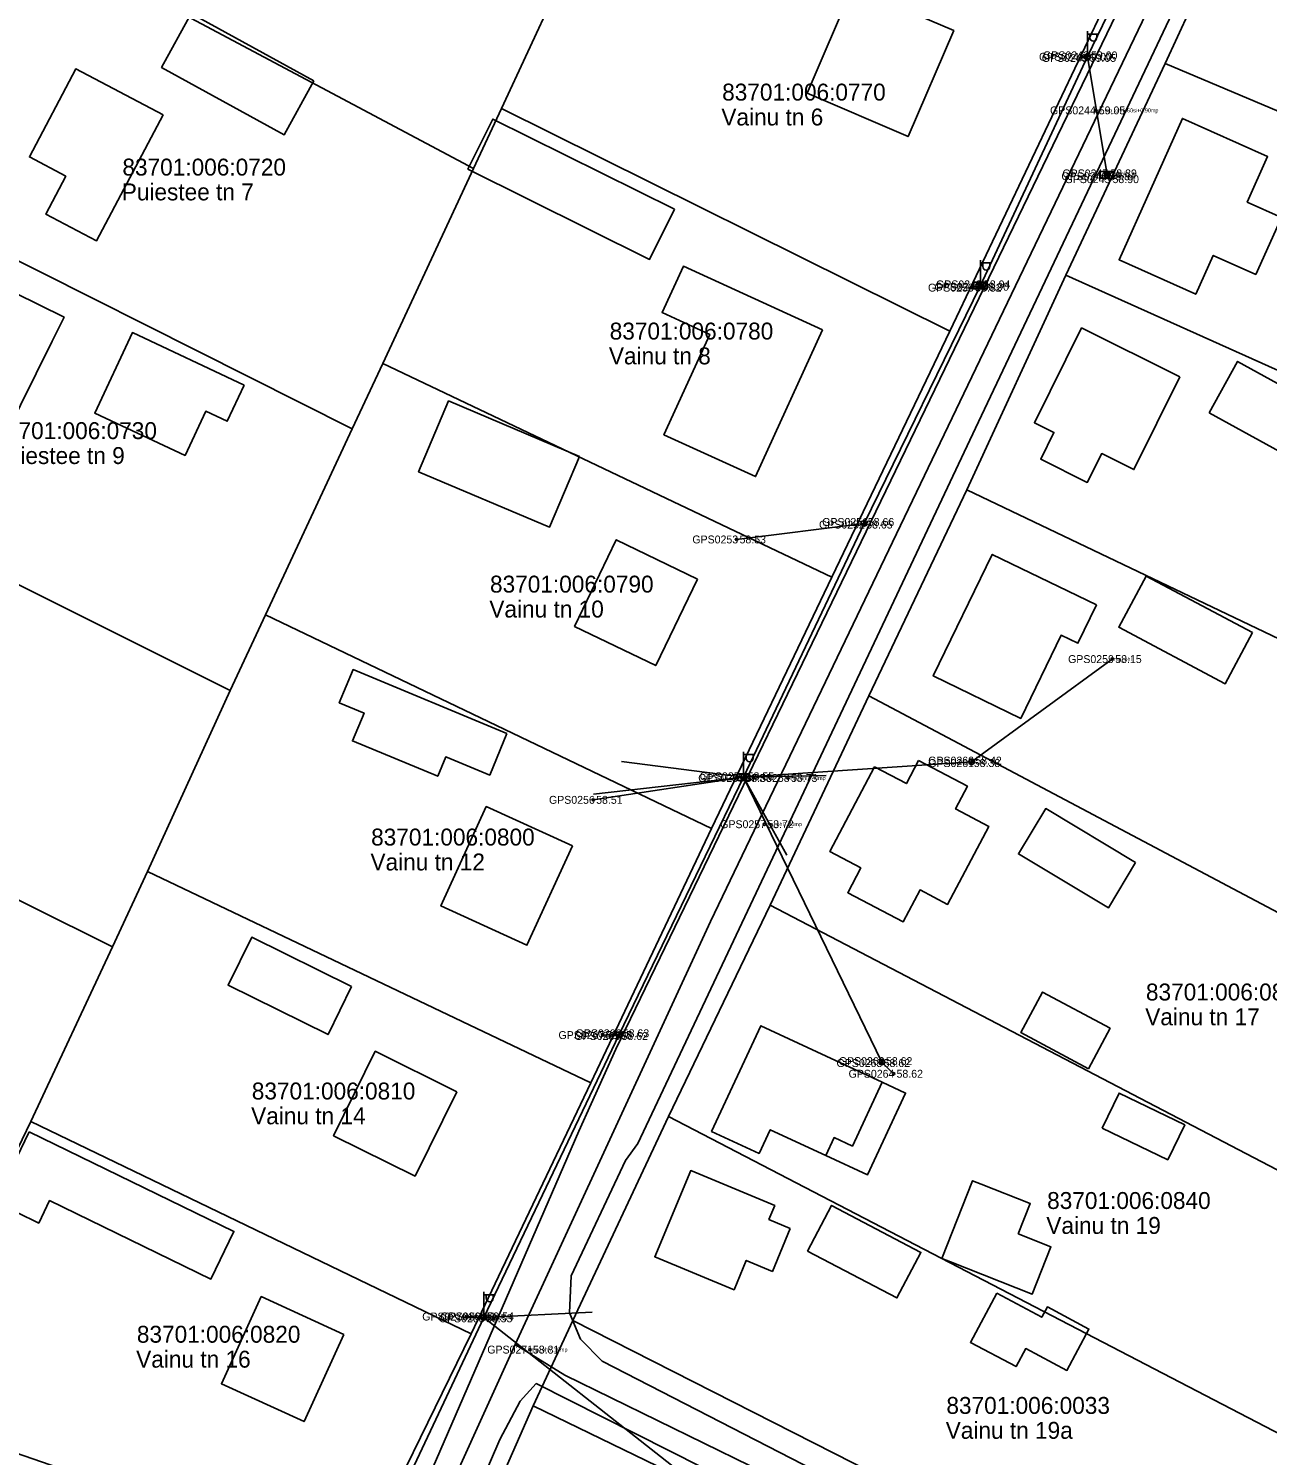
# Model space of a CAD drawing. Extents: x 580119 to 583377, y 6518915 to 6520820.
# Drawn here: x 581528.3 to 581638.1, y 6519438.4 to 6519564.9 of the extents above; entities that cross this region are included whole.
import ezdxf

# ---------------------------------------------------------------- set-up
doc = ezdxf.new("R2010")
doc.units = 0
for name, color, linetype in [('ELRAJATISMP', 7, 'Continuous'), ('Hoone Elu- või ühiskondlik hoone', 7, 'Continuous'), ('Hoone Kõrval- või tootmishoone', 7, 'Continuous'), ('L_AADRESS', 7, 'Continuous'), ('MAAMUDEL', 7, 'Continuous'), ('MOOTKORG-EH2000', 7, 'Continuous'), ('MOOTMPUNKT', 7, 'Continuous'), ('MOOTNR', 7, 'Continuous'), ('MPOHULIIN', 7, 'Continuous'), ('Muu rajatis Katusealune', 7, 'Continuous'), ('PIIR', 7, 'Continuous'), ('POST', 7, 'Continuous'), ('Rippe kõrgus', 7, 'Continuous'), ('SIOHULIIN', 7, 'Continuous'), ('SIRAJATIS', 7, 'Continuous'), ('Tee Liiklusala', 7, 'Continuous'), ('Tee Tänav Püsikate', 7, 'Continuous'), ('TUNNUS', 7, 'Continuous')]:
    doc.layers.add(name, color=color, linetype=linetype)

msp = doc.modelspace()

# ---------------------------------------------------------------- linework, layer by layer
at = {"layer": 'ELRAJATISMP'}
for p, q in [((581623.73, 6519552.23), (581623.73, 6519551.63)), ((581624, 6519552.23), (581624, 6519551.63)), ((581612.5, 6519542.41), (581612.5, 6519541.81)), ((581612.77, 6519542.41), (581612.77, 6519541.81))]:
    msp.add_line(p, q, dxfattribs=at)
for points in [[(581623.27, 6519552.23), (581624.46, 6519552.23), (581624.46, 6519551.63), (581623.27, 6519551.63)], [(581612.04, 6519542.41), (581613.24, 6519542.41), (581613.24, 6519541.81), (581612.04, 6519541.81)]]:
    msp.add_lwpolyline(points, close=True, dxfattribs=at)
at = {"layer": 'Hoone Elu- või ühiskondlik hoone'}
for points in [[(581597.28, 6519559.17), (581601.32, 6519568.57), (581610.28, 6519564.72), (581606.24, 6519555.32)], [(581540.18, 6519557.24), (581534.28, 6519546.07), (581529.78, 6519548.45), (581531.56, 6519551.8), (581528.33, 6519553.51), (581532.45, 6519561.32)], [(581639.34, 6519548.15), (581637.06, 6519543.09), (581633.29, 6519544.78), (581631.74, 6519541.33), (581624.94, 6519544.39), (581630.56, 6519556.93), (581638.11, 6519553.54), (581636.31, 6519549.51)], [(581598.66, 6519538.18), (581592.71, 6519525.16), (581584.58, 6519528.88), (581588.65, 6519537.78), (581584.43, 6519539.71), (581586.31, 6519543.82)], [(581522.34, 6519541.1), (581526, 6519539.3), (581527.05, 6519541.46), (581531.41, 6519539.31), (581530.35, 6519537.16), (581526.14, 6519528.62), (581518.14, 6519532.56)], [(581630.33, 6519534.01), (581626.25, 6519525.79), (581623.4, 6519527.21), (581622.12, 6519524.65), (581617.99, 6519526.7), (581619.17, 6519529.08), (581617.43, 6519529.94), (581621.62, 6519538.35)], [(581587.57, 6519516.08), (581583.87, 6519508.4), (581576.66, 6519511.88), (581580.36, 6519519.56)], [(581622.95, 6519513.78), (581621.29, 6519510.38), (581619.8, 6519511.1), (581616.22, 6519503.72), (581608.46, 6519507.49), (581613.69, 6519518.27)], [(581607.16, 6519499.98), (581611.5, 6519497.7), (581610.45, 6519495.7), (581613.39, 6519494.15), (581609.73, 6519487.22), (581607.3, 6519488.52), (581605.79, 6519485.68), (581600.88, 6519488.26), (581602.04, 6519490.46), (581599.31, 6519491.91), (581603.27, 6519499.42), (581606.08, 6519497.94)], [(581576.47, 6519492.41), (581572.44, 6519483.6), (581564.82, 6519487.09), (581568.84, 6519495.9)], [(581603.94, 6519471.46), (581601.3, 6519465.79), (581599.67, 6519466.55), (581598.93, 6519464.96), (581594.01, 6519467.25), (581593.03, 6519465.14), (581588.82, 6519467.1), (581593.19, 6519476.47)], [(581566.24, 6519470.61), (581562.52, 6519463.13), (581555.3, 6519466.72), (581559, 6519474.2)], [(581595.79, 6519458.5), (581594.2, 6519454.69), (581591.89, 6519455.66), (581590.81, 6519453.05), (581583.77, 6519455.99), (581586.96, 6519463.63), (581594.41, 6519460.52), (581593.9, 6519459.29)], [(581556.22, 6519449.09), (581552.68, 6519441.36), (581545.35, 6519444.72), (581548.89, 6519452.45)]]:
    msp.add_lwpolyline(points, close=True, dxfattribs=at)
at = {"layer": 'Hoone Kõrval- või tootmishoone'}
for points in [[(581553.56, 6519560.25), (581550.92, 6519555.46), (581540.05, 6519561.45), (581542.69, 6519566.24)], [(581585.52, 6519548.87), (581583.31, 6519544.43), (581567.21, 6519552.43), (581569.41, 6519556.87)], [(581547.38, 6519533.28), (581545.88, 6519530.07), (581543.97, 6519530.96), (581542.13, 6519527.04), (581534.13, 6519530.8), (581537.47, 6519537.93)], [(581632.93, 6519530.83), (581635.44, 6519535.38), (581643.45, 6519530.96), (581640.94, 6519526.41)], [(581577.09, 6519526.95), (581574.43, 6519520.67), (581562.83, 6519525.59), (581565.5, 6519531.87)], [(581636.76, 6519511.34), (581634.35, 6519506.79), (581624.91, 6519511.81), (581627.33, 6519516.35)], [(581570.67, 6519502.37), (581569.15, 6519498.69), (581565.24, 6519500.3), (581564.53, 6519498.59), (581556.97, 6519501.73), (581558, 6519504.19), (581555.81, 6519505.11), (581557.03, 6519508.05)], [(581626.4, 6519490.95), (581623.99, 6519486.92), (581616.02, 6519491.7), (581618.44, 6519495.72)], [(581556.9, 6519479.94), (581554.81, 6519475.69), (581545.95, 6519480.08), (581548.05, 6519484.32)], [(581622.23, 6519472.66), (581616.24, 6519475.86), (581618.16, 6519479.45), (581624.14, 6519476.25)], [(581528.32, 6519467.05), (581546.47, 6519458.23), (581544.42, 6519454.01), (581530.13, 6519460.96), (581529.17, 6519458.97), (581525.3, 6519460.85)], [(581616, 6519458.01), (581618.89, 6519456.87), (581617.24, 6519452.67), (581610, 6519455.52), (581609.23, 6519455.83), (581611.94, 6519462.72), (581612.71, 6519462.41), (581617.06, 6519460.7)], [(581597.33, 6519456.49), (581599.45, 6519460.53), (581607.37, 6519456.37), (581605.24, 6519452.33)], [(581614.09, 6519452.75), (581618.09, 6519450.62), (581618.58, 6519451.54), (581622.27, 6519449.57), (581620.31, 6519445.9), (581616.66, 6519447.84), (581615.81, 6519446.24), (581611.76, 6519448.39)]]:
    msp.add_lwpolyline(points, close=True, dxfattribs=at)
at = {"layer": 'MOOTMPUNKT'}
for centre in [(581621.69, 6519562.39), (581622.08, 6519562.29), (581622.19, 6519562.52), (581622.88, 6519557.64), (581623.82, 6519551.8), (581623.91, 6519552.05), (581624.1, 6519551.54), (581611.92, 6519541.92), (581612.57, 6519542), (581612.7, 6519542.21), (581602.26, 6519520.91), (581602.4, 6519521.14), (581591.03, 6519519.59), (581624.34, 6519508.98), (581611.94, 6519499.98), (581591.75, 6519498.59), (581611.8, 6519499.76), (581591.55, 6519498.44), (581595.59, 6519498.44), (581578.32, 6519496.5), (581593.49, 6519494.34), (581580.68, 6519475.8), (581579.16, 6519475.64), (581580.57, 6519475.56), (581604.01, 6519473.33), (581603.81, 6519473.16), (581604.95, 6519472.21), (581567.08, 6519450.68), (581568.55, 6519450.52), (581568.68, 6519450.69), (581572.71, 6519447.75)]:
    msp.add_circle(centre, 0.1, dxfattribs=at)
at = {"layer": 'MPOHULIIN'}
for p, q in [((581602.33, 6519521.02), (581591.03, 6519519.59)), ((581579.16, 6519475.64), (581580.62, 6519475.68))]:
    msp.add_line(p, q, dxfattribs=at)
for points in [[(581634.1, 6519587.2), (581622.13, 6519562.41), (581621.69, 6519562.39)], [(581622.13, 6519562.41), (581612.64, 6519542.11), (581611.92, 6519541.92)], [(581622.13, 6519562.41), (581623.87, 6519551.93), (581624.1, 6519551.54)], [(581612.64, 6519542.11), (581602.33, 6519521.02), (581591.65, 6519498.51), (581580.62, 6519475.68), (581568.62, 6519450.61), (581558.9, 6519429.94), (581550.83, 6519409.48), (581555.87, 6519383.2), (581556.26, 6519380.71)], [(581591.65, 6519498.51), (581611.87, 6519499.87), (581624.34, 6519508.98)], [(581578.32, 6519496.5), (581591.65, 6519498.51), (581603.91, 6519473.25)], [(581603.91, 6519473.25), (581604.95, 6519472.21)], [(581585.66, 6519437.19), (581568.62, 6519450.61), (581567.08, 6519450.68)]]:
    msp.add_lwpolyline(points, dxfattribs=at)
at = {"layer": 'Muu rajatis Katusealune'}
for points in [[(581598.93, 6519464.96), (581599.67, 6519466.55), (581601.3, 6519465.79), (581603.94, 6519471.46), (581606.01, 6519470.49), (581602.63, 6519463.24)], [(581623.45, 6519467.4), (581624.94, 6519470.49), (581630.76, 6519467.67), (581629.26, 6519464.58)]]:
    msp.add_lwpolyline(points, close=True, dxfattribs=at)
at = {"layer": 'PIIR'}
for points in [[(581557.23, 6519428.16), (581567.49, 6519449.14), (581578.1, 6519471.41), (581588.81, 6519493.97), (581599.48, 6519516.26), (581609.94, 6519538.07), (581623.95, 6519567.52), (581642.61, 6519606.31), (581662.45, 6519648.25)], [(581713.76, 6519630.56), (581711.33, 6519626.84), (581668.3, 6519646.83), (581659, 6519625.86), (581648.38, 6519603.83), (581638.88, 6519583.1), (581629.02, 6519561.79), (581620.23, 6519543.03), (581611.43, 6519523.99), (581602.74, 6519505.71), (581594.01, 6519487.16), (581585, 6519468.42), (581576.5, 6519450.32), (581573, 6519442.77), (581564.16, 6519422.65)]]:
    msp.add_lwpolyline(points, dxfattribs=at)
for points in [[(581540.44, 6519597.74), (581579.53, 6519577.94), (581570.18, 6519557.8), (581567.7, 6519552.5), (581527.81, 6519573.75)], [(581638.88, 6519583.1), (581711.27, 6519552.36), (581701.95, 6519531.01), (581629.02, 6519561.79)], [(581579.53, 6519577.94), (581579.76, 6519578.36), (581623.95, 6519567.52), (581609.94, 6519538.07), (581570.18, 6519557.8)], [(581527.81, 6519573.75), (581567.7, 6519552.5), (581559.66, 6519535.2), (581556.96, 6519529.39), (581515.58, 6519550.2)], [(581629.02, 6519561.79), (581701.95, 6519531.01), (581694.24, 6519513.34), (581693.81, 6519509.99), (581620.23, 6519543.03)], [(581567.7, 6519552.5), (581570.18, 6519557.8), (581609.94, 6519538.07), (581599.48, 6519516.26), (581559.66, 6519535.2)], [(581515.58, 6519550.2), (581556.96, 6519529.39), (581549.28, 6519512.9), (581546.14, 6519506.19), (581503.84, 6519527.33)], [(581620.23, 6519543.03), (581693.81, 6519509.99), (581689.89, 6519486.51), (581611.43, 6519523.99)], [(581556.96, 6519529.39), (581559.66, 6519535.2), (581599.48, 6519516.26), (581588.81, 6519493.97), (581549.28, 6519512.9)], [(581503.84, 6519527.33), (581546.14, 6519506.19), (581538.79, 6519490.14), (581535.7, 6519483.46), (581492.04, 6519505.18)], [(581611.43, 6519523.99), (581689.89, 6519486.51), (581688.7, 6519480.42), (581677.83, 6519483.43), (581671.38, 6519469.38), (581602.74, 6519505.71)], [(581789.1, 6519512.64), (581795.63, 6519521.82), (581803.96, 6519517.1), (581765.77, 6519467.95), (581737.28, 6519431.53), (581727.74, 6519419.24), (581710.26, 6519397.63), (581687.53, 6519368.94), (581678.62, 6519376.59), (581684.75, 6519384.2), (581642.32, 6519408.42), (581613.99, 6519422.86), (581573, 6519442.77), (581576.5, 6519450.32), (581645.82, 6519415.09), (581688.07, 6519391.74), (581690.75, 6519391.53), (581702.7, 6519406.25), (581723.83, 6519432.5), (581747.92, 6519461.48), (581763.53, 6519480.96)], [(581546.14, 6519506.19), (581549.28, 6519512.9), (581588.81, 6519493.97), (581578.1, 6519471.41), (581538.79, 6519490.14)], [(581492.04, 6519505.18), (581535.7, 6519483.46), (581528.47, 6519467.97), (581526.15, 6519463.18), (581480.98, 6519483.53)], [(581602.74, 6519505.71), (581671.38, 6519469.38), (581669.21, 6519464.65), (581663.01, 6519451.13), (581594.01, 6519487.16)], [(581535.7, 6519483.46), (581538.79, 6519490.14), (581578.1, 6519471.41), (581567.49, 6519449.14), (581528.47, 6519467.97)], [(581594.01, 6519487.16), (581663.01, 6519451.13), (581658.7, 6519442.22), (581653.76, 6519432.69), (581585, 6519468.42)], [(581576.5, 6519450.32), (581585, 6519468.42), (581653.76, 6519432.69), (581645.82, 6519415.09)], [(581526.15, 6519463.18), (581528.47, 6519467.97), (581567.49, 6519449.14), (581557.23, 6519428.16), (581523.23, 6519439.92), (581516.47, 6519442.27)], [(581573, 6519442.77), (581613.99, 6519422.86), (581604.36, 6519402.62), (581564.16, 6519422.65)]]:
    msp.add_lwpolyline(points, close=True, dxfattribs=at)
at = {"layer": 'POST'}
for p, q in [((581622.13, 6519562.66), (581622.13, 6519564.66)), ((581622.13, 6519564.41), (581623.13, 6519564.41)), ((581622.36, 6519564.09), (581622.36, 6519564.41)), ((581622.97, 6519564.09), (581622.97, 6519564.41)), ((581622.13, 6519562.41), (581622.13, 6519562.41)), ((581612.64, 6519542.36), (581612.64, 6519544.36)), ((581612.64, 6519544.11), (581613.64, 6519544.11)), ((581612.86, 6519543.79), (581612.86, 6519544.11)), ((581613.48, 6519543.79), (581613.48, 6519544.11)), ((581612.64, 6519542.11), (581612.64, 6519542.11)), ((581591.65, 6519498.76), (581591.65, 6519500.76)), ((581591.65, 6519500.51), (581592.65, 6519500.51)), ((581591.88, 6519500.19), (581591.88, 6519500.51)), ((581592.49, 6519500.19), (581592.49, 6519500.51)), ((581591.65, 6519498.51), (581591.65, 6519498.51)), ((581568.62, 6519450.86), (581568.62, 6519452.86)), ((581568.62, 6519452.61), (581569.62, 6519452.61)), ((581568.84, 6519452.29), (581568.84, 6519452.61)), ((581569.46, 6519452.29), (581569.46, 6519452.61)), ((581568.62, 6519450.61), (581568.62, 6519450.61))]:
    msp.add_line(p, q, dxfattribs=at)
for centre in [(581622.13, 6519562.41), (581623.87, 6519551.93), (581612.64, 6519542.11), (581602.33, 6519521.02), (581611.87, 6519499.87), (581591.65, 6519498.51), (581580.62, 6519475.68), (581603.91, 6519473.25), (581568.62, 6519450.61)]:
    msp.add_circle(centre, 0.25, dxfattribs=at)
for centre in [(581622.66, 6519564.09), (581613.17, 6519543.79), (581592.18, 6519500.19), (581569.15, 6519452.29)]:
    msp.add_arc(centre, 0.306, 180, 0, dxfattribs=at)
at = {"layer": 'SIOHULIIN'}
for p, q in [((581591.65, 6519498.51), (581580.84, 6519499.91)), ((581591.65, 6519498.51), (581598.96, 6519498.65)), ((581591.65, 6519498.51), (581578.34, 6519496.99)), ((581591.65, 6519498.51), (581595.48, 6519491.6)), ((581568.62, 6519450.61), (581566.81, 6519450.6))]:
    msp.add_line(p, q, dxfattribs=at)
for points in [[(581633.31, 6519588), (581634.1, 6519587.2), (581622.13, 6519562.41), (581623.87, 6519551.93)], [(581622.13, 6519562.41), (581612.64, 6519542.11), (581602.33, 6519521.02), (581591.65, 6519498.51)], [(581591.65, 6519498.51), (581580.62, 6519475.68), (581568.62, 6519450.61), (581578.23, 6519451.08)]]:
    msp.add_lwpolyline(points, dxfattribs=at)
at = {"layer": 'SIRAJATIS'}
msp.add_lwpolyline([(581591.15, 6519498.81), (581592.15, 6519498.81), (581592.15, 6519498.21), (581591.15, 6519498.21)], close=True, dxfattribs=at)
for centre, radius in [((581591.45, 6519498.51), 0.0304), ((581591.45, 6519498.51), 0.029), ((581591.45, 6519498.51), 0.0277), ((581591.45, 6519498.51), 0.0263), ((581591.45, 6519498.51), 0.0249), ((581591.45, 6519498.51), 0.0236), ((581591.45, 6519498.51), 0.0222), ((581591.45, 6519498.51), 0.0209), ((581591.45, 6519498.51), 0.0195), ((581591.45, 6519498.51), 0.0181), ((581591.45, 6519498.51), 0.0168), ((581591.45, 6519498.51), 0.0154), ((581591.45, 6519498.51), 0.014), ((581591.45, 6519498.51), 0.0127), ((581591.45, 6519498.51), 0.0113), ((581591.45, 6519498.51), 0.00996), ((581591.45, 6519498.51), 0.0086), ((581591.45, 6519498.51), 0.00724), ((581591.45, 6519498.51), 0.00587), ((581591.45, 6519498.51), 0.00451), ((581591.45, 6519498.51), 0.00315), ((581591.45, 6519498.51), 0.00179), ((581591.45, 6519498.51), 0.000426), ((581591.85, 6519498.51), 0.0304), ((581591.85, 6519498.51), 0.029), ((581591.85, 6519498.51), 0.0277), ((581591.85, 6519498.51), 0.0263), ((581591.85, 6519498.51), 0.0249), ((581591.85, 6519498.51), 0.0236), ((581591.85, 6519498.51), 0.0222), ((581591.85, 6519498.51), 0.0209), ((581591.85, 6519498.51), 0.0195), ((581591.85, 6519498.51), 0.0181), ((581591.85, 6519498.51), 0.0168), ((581591.85, 6519498.51), 0.0154), ((581591.85, 6519498.51), 0.014), ((581591.85, 6519498.51), 0.0127), ((581591.85, 6519498.51), 0.0113), ((581591.85, 6519498.51), 0.00996), ((581591.85, 6519498.51), 0.0086), ((581591.85, 6519498.51), 0.00724), ((581591.85, 6519498.51), 0.00587), ((581591.85, 6519498.51), 0.00451), ((581591.85, 6519498.51), 0.00315), ((581591.85, 6519498.51), 0.00179), ((581591.85, 6519498.51), 0.000426)]:
    msp.add_circle(centre, radius, dxfattribs=at)
at = {"layer": 'Tee Liiklusala'}
for points in [[(581551.14, 6519407.39), (581577.04, 6519467.13), (581580.33, 6519474.4), (581634.29, 6519586.04), (581644.12, 6519607.31), (581696.84, 6519718.1)], [(581662.25, 6519633.41), (581639.04, 6519586.12), (581612.21, 6519529.46), (581582.28, 6519466.02), (581581.18, 6519464.51), (581576.35, 6519454.3), (581576.22, 6519451), (581577.2, 6519448.68), (581579.11, 6519446.72), (581601.13, 6519435.39)], [(581590.93, 6519435.81), (581573.25, 6519444.73), (581571.83, 6519443.19), (581570.03, 6519439.79), (581555.37, 6519405.77)]]:
    msp.add_lwpolyline(points, dxfattribs=at)
at = {"layer": 'Tee Tänav Püsikate'}
for points in [[(581571.4, 6519448.2), (581588.72, 6519485.71), (581629.79, 6519571.37), (581666.47, 6519649.43)], [(581571.4, 6519448.2), (581566.3, 6519436.94), (581553.31, 6519406.62)], [(581691.88, 6519386.55), (581684.87, 6519389.83), (581671.82, 6519397.68), (581612.76, 6519427.38), (581575.8, 6519445.49), (581571.4, 6519448.2)]]:
    msp.add_lwpolyline(points, dxfattribs=at)

# ---------------------------------------------------------------- texts
at = {"layer": 'L_AADRESS'}
for s, p in [('Vainu tn 6', (581589.68, 6519556.3)), ('Puiestee tn 7', (581536.52, 6519549.66)), ('Vainu tn 8', (581579.71, 6519535.12)), ('Puiestee tn 9', (581525.08, 6519526.28)), ('Vainu tn 10', (581569.11, 6519512.67)), ('Vainu tn 12', (581558.57, 6519490.24)), ('Vainu tn 17', (581627.26, 6519476.51)), ('Vainu tn 14', (581547.99, 6519467.73)), ('Vainu tn 19', (581618.49, 6519458.01)), ('Vainu tn 16', (581537.8, 6519446.15)), ('Vainu tn 19a', (581609.57, 6519439.84))]:
    msp.add_text(s, height=1.5, dxfattribs=at).set_placement(p)
at = {"layer": 'MAAMUDEL'}
for s, p in [(' kaabel', (581623.82, 6519551.63)), (' kaabel', (581623.91, 6519551.88)), (' mp_ohl', (581624.34, 6519508.81)), (' mp_ohl7.40mp', (581595.59, 6519498.26)), (' mp_ohl7.20mp', (581593.49, 6519494.17)), (' kaabel', (581568.55, 6519450.35)), (' kaabel', (581568.68, 6519450.52)), (' mp_ohl7.10mp', (581572.71, 6519447.57))]:
    msp.add_text(s, height=0.35, dxfattribs=at).set_placement(p)
at = {"layer": 'MOOTKORG-EH2000'}
for s, p in [(' 59.00', (581621.69, 6519562.04)), (' 59.05', (581622.08, 6519561.94)), (' 59.00', (581622.19, 6519562.17)), (' 59.05', (581622.88, 6519557.29)), (' 58.84', (581623.82, 6519551.45)), (' 58.89', (581623.91, 6519551.7)), (' 58.90', (581624.1, 6519551.19)), (' 58.82', (581611.92, 6519541.57)), (' 58.90', (581612.57, 6519541.65)), (' 58.94', (581612.7, 6519541.86)), (' 58.66', (581602.4, 6519520.79)), (' 58.65', (581602.26, 6519520.56)), (' 58.53', (581591.03, 6519519.24)), (' 58.15', (581624.34, 6519508.63)), (' 58.38', (581611.8, 6519499.41)), (' 58.42', (581611.94, 6519499.63)), (' 58.53', (581591.55, 6519498.09)), (' 58.55', (581591.75, 6519498.24)), (' 58.73', (581595.59, 6519498.09)), (' 58.51', (581578.32, 6519496.15)), (' 58.72', (581593.49, 6519493.99)), (' 58.95', (581579.16, 6519475.29)), (' 58.62', (581580.57, 6519475.21)), (' 58.63', (581580.68, 6519475.45)), (' 58.62', (581603.81, 6519472.81)), (' 58.62', (581604.01, 6519472.98)), (' 58.62', (581604.95, 6519471.86)), (' 59.01', (581567.08, 6519450.33)), (' 58.53', (581568.55, 6519450.17)), (' 58.54', (581568.68, 6519450.34)), (' 58.81', (581572.71, 6519447.4))]:
    msp.add_text(s, height=0.7, dxfattribs=at).set_placement(p)
at = {"layer": 'MOOTNR'}
for s, p in [('GPS0241 ', (581617.84, 6519562.04)), ('GPS0243 ', (581618.09, 6519561.94)), ('GPS0242 ', (581618.2, 6519562.17)), ('GPS0244 ', (581618.82, 6519557.29)), ('GPS0246 ', (581619.83, 6519551.45)), ('GPS0247 ', (581619.92, 6519551.7)), ('GPS0245 ', (581620.11, 6519551.19)), ('GPS0250 ', (581608, 6519541.57)), ('GPS0248 ', (581608.58, 6519541.65)), ('GPS0249 ', (581608.71, 6519541.86)), ('GPS0251 ', (581598.62, 6519520.79)), ('GPS0252 ', (581598.34, 6519520.56)), ('GPS0253 ', (581587.11, 6519519.24)), ('GPS0259 ', (581620.42, 6519508.63)), ('GPS0260 ', (581608.02, 6519499.63)), ('GPS0261 ', (581608.02, 6519499.41)), ('GPS0255 ', (581587.63, 6519498.09)), ('GPS0254 ', (581587.76, 6519498.24)), ('GPS0258 ', (581591.67, 6519498.09)), ('GPS0256 ', (581574.4, 6519496.15)), ('GPS0257 ', (581589.58, 6519493.99)), ('GPS0267 ', (581575.24, 6519475.29)), ('GPS0265 ', (581576.65, 6519475.21)), ('GPS0266 ', (581576.76, 6519475.45)), ('GPS0263 ', (581599.89, 6519472.81)), ('GPS0262 ', (581600.09, 6519472.98)), ('GPS0264 ', (581600.96, 6519471.86)), ('GPS0270 ', (581563.16, 6519450.33)), ('GPS0268 ', (581564.63, 6519450.17)), ('GPS0269 ', (581564.77, 6519450.34)), ('GPS0271 ', (581568.93, 6519447.4))]:
    msp.add_text(s, height=0.7, dxfattribs=at).set_placement(p)
at = {"layer": 'Rippe kõrgus'}
msp.add_text(' el_mp_ohl6.60si+0.90mp', height=0.35, dxfattribs=at).set_placement((581622.88, 6519557.46))
at = {"layer": 'TUNNUS'}
for s, p in [('83701:006:0770', (581589.75, 6519558.51)), ('83701:006:0720', (581536.58, 6519551.86)), ('83701:006:0780', (581579.78, 6519537.32)), ('83701:006:0730', (581525.14, 6519528.49)), ('83701:006:0790', (581569.17, 6519514.88)), ('83701:006:0800', (581558.63, 6519492.45)), ('83701:006:0830', (581627.32, 6519478.71)), ('83701:006:0810', (581548.05, 6519469.93)), ('83701:006:0840', (581618.56, 6519460.22)), ('83701:006:0820', (581537.86, 6519448.36)), ('83701:006:0033', (581609.63, 6519442.05))]:
    msp.add_text(s, height=1.5, dxfattribs=at).set_placement(p)

doc.saveas('drawing.dxf')
